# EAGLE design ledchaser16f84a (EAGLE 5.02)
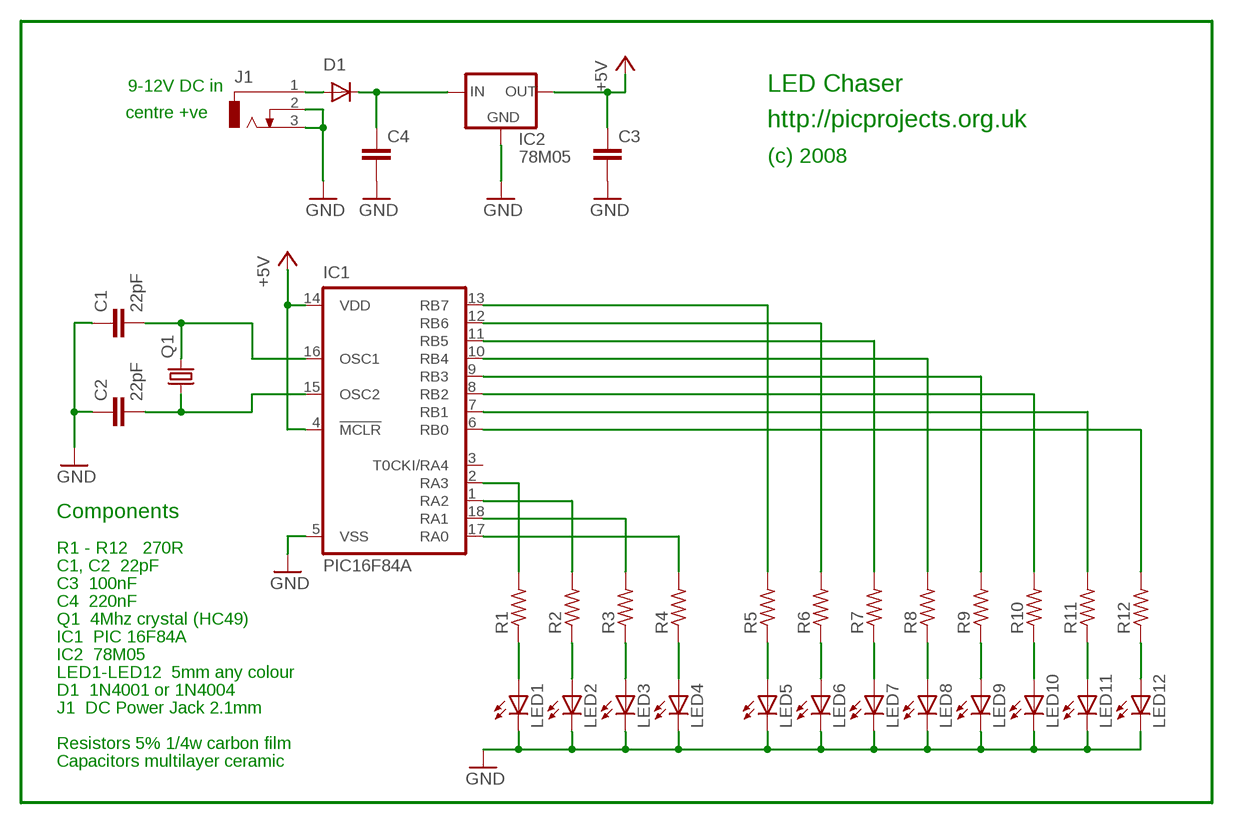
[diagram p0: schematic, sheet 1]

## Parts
C1  22pF  C-EU025-024X044  [C025-024X044]
C2  22pF  C-EU025-024X044  [C025-024X044]
C3  C-EU025-040X050  [C025-040X050]
C4  C-EU025-040X050  [C025-040X050]
D1  1N4004  [DO41-10]
IC1  PIC16F84A  PIC16F83P  [DIL18]
IC2  78M05  78XXL  [78XXL]
J1  DCJ0202  [DCJ0202]
LED1  LED5MM  [LED5MM]
LED2  LED5MM  [LED5MM]
LED3  LED5MM  [LED5MM]
LED4  LED5MM  [LED5MM]
LED5  LED5MM  [LED5MM]
LED6  LED5MM  [LED5MM]
LED7  LED5MM  [LED5MM]
LED8  LED5MM  [LED5MM]
LED9  LED5MM  [LED5MM]
LED10  LED5MM  [LED5MM]
LED11  LED5MM  [LED5MM]
LED12  LED5MM  [LED5MM]
Q1  CRYSTALHC49S  [HC49/S]
R1  R-US_0207/12  [0207/12]
R2  R-US_0207/12  [0207/12]
R3  R-US_0207/12  [0207/12]
R4  R-US_0207/12  [0207/12]
R5  R-US_0207/12  [0207/12]
R6  R-US_0207/12  [0207/12]
R7  R-US_0207/12  [0207/12]
R8  R-US_0207/12  [0207/12]
R9  R-US_0207/12  [0207/12]
R10  R-US_0207/12  [0207/12]
R11  R-US_0207/12  [0207/12]
R12  R-US_0207/12  [0207/12]

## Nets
+5V: C3.1 IC1.4(!MCLR) IC1.14(VDD) IC2.OUT
GND: C1.1 C2.1 C3.2 C4.2 IC1.5(VSS) IC2.GND J1.2 J1.3 LED1.K(C) LED2.K(C) LED3.K(C) LED4.K(C) LED5.K(C) LED6.K(C) LED7.K(C) LED8.K(C) LED9.K(C) LED10.K(C) LED11.K(C) LED12.K(C)
N$1: LED1.A R1.1
N$2: C2.2 IC1.15(OSC2) Q1.1
N$3: C1.2 IC1.16(OSC1) Q1.2
N$4: LED2.A R2.1
N$5: LED3.A R3.1
N$6: LED4.A R4.1
N$7: LED5.A R5.1
N$8: LED6.A R6.1
N$9: LED7.A R7.1
N$10: LED8.A R8.1
N$11: LED9.A R9.1
N$12: LED10.A R10.1
N$13: LED11.A R11.1
N$14: LED12.A R12.1
N$15: IC1.17(RA0) R4.2
N$16: IC1.18(RA1) R3.2
N$17: IC1.1(RA2) R2.2
N$18: IC1.2(RA3) R1.2
N$19: IC1.6(RB0) R12.2
N$20: IC1.7(RB1) R11.2
N$21: IC1.8(RB2) R10.2
N$22: IC1.9(RB3) R9.2
N$23: IC1.10(RB4) R8.2
N$24: IC1.11(RB5) R7.2
N$25: IC1.12(RB6) R6.2
N$26: IC1.13(RB7) R5.2
N$27 [power]: D1.A J1.1
N$28 [power]: C4.1 D1.C IC2.IN
Unconnected: IC1.3(T0CKI/RA4)

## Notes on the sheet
- 9-12V DC in | LED Chaser
- centre +ve
- http://picprojects.org.uk
- (c) 2008
- Components
- R1 - R12   270R
- C1, C2  22pF
- C3  100nF
- C4  220nF
- Q1  4Mhz crystal (HC49)
- IC1  PIC 16F84A
- IC2  78M05
- LED1-LED12  5mm any colour
- D1  1N4001 or 1N4004
- J1  DC Power Jack 2.1mm
- Resistors 5% 1/4w carbon film
- Capacitors multilayer ceramic

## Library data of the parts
C1-C4 = rcl:C-EU: CAPACITOR, European symbol
D1 = diode:1N4004: DIODE
IC1 = microchip:PIC16F8*: MICROCONTROLLER 8-Bit PIC16F8X Family - CMOS Flash/EEPROM Pin Compatible : PIC16F83, PIC16CR83, PIC16F84A, PIC16CR84 see also PIC16C*
IC2 = v-reg:78XXL: VOLTAGE REGULATOR
J1 = con-jack:DCJ0202: DC POWER JACK Source: DCJ0202.pdf
LED1-LED12 = led:LED: LED
Q1 = crystal:CRYSTAL: CRYSTAL
R1-R12 = rcl:R-US_: RESISTOR, American symbol

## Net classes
0 default: width 0.61 mm
1 power: width 0.914 mm

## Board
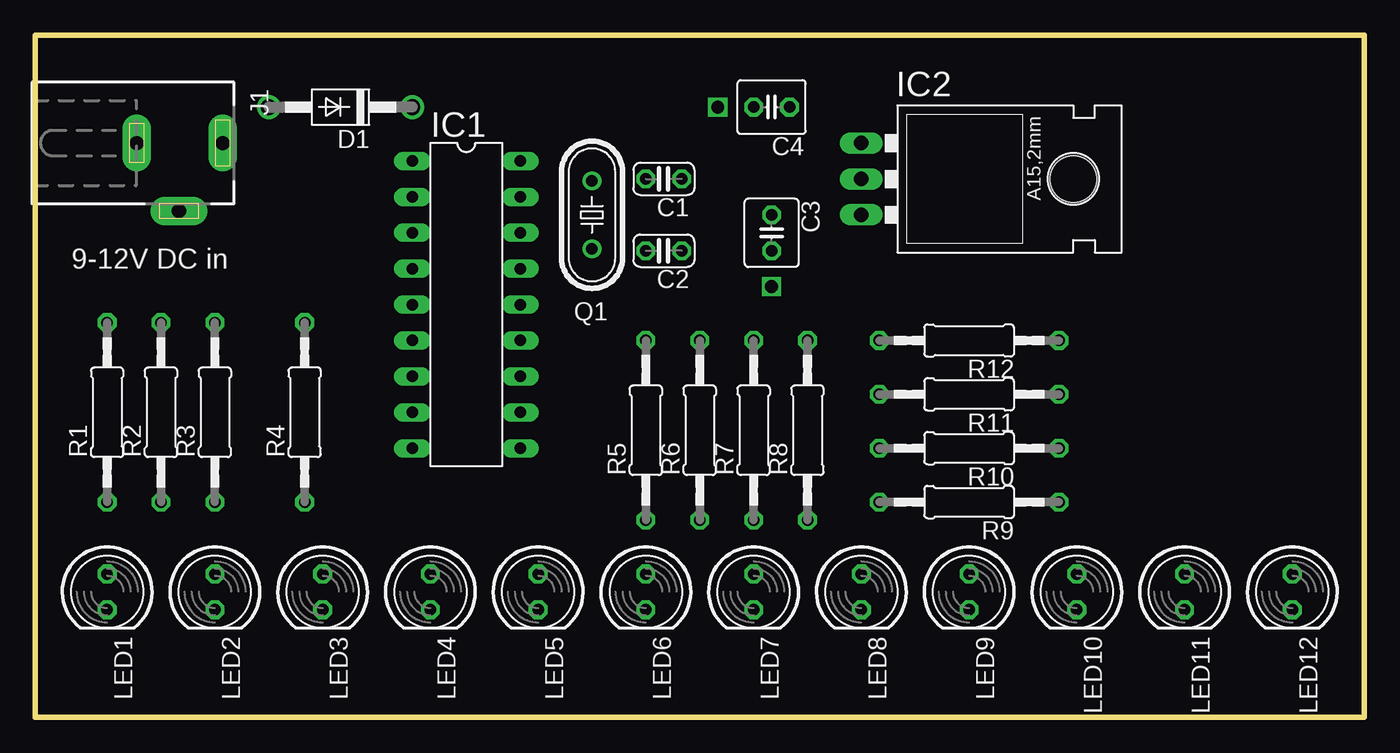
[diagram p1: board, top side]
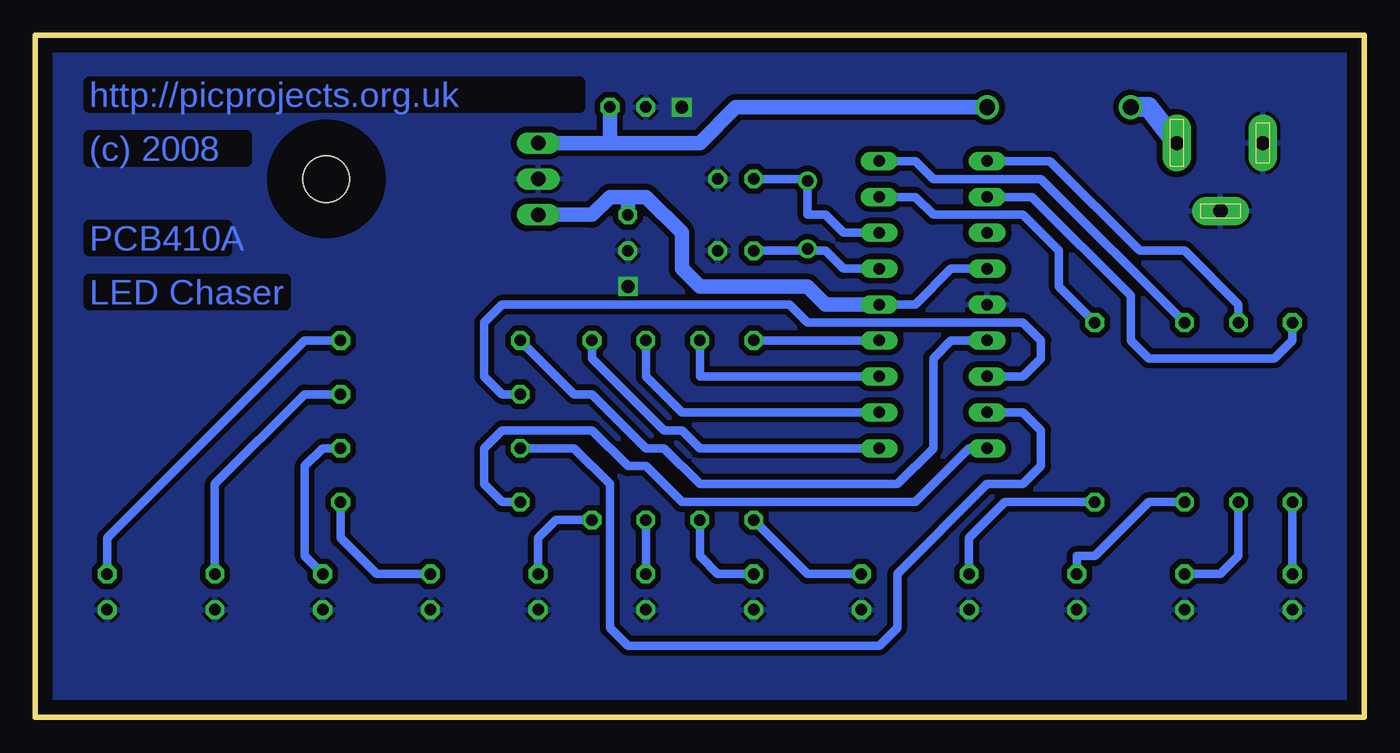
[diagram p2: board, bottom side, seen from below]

Size 93.98 x 48.26 mm. Coordinates in mm from the lower left corner, seen from the top.
Outline: 0,48.26 93.98,48.26 93.98,0 0,0 0,48.26
Copper layers (1*16): Top 0.035mm / dielectric 1.5mm / Bottom 0.035mm
Design rules "default *": minimum track width 10mil, minimum drill 24mil, track to track 16mil, track to pad 16mil, pad to pad 8mil, via to via 8mil, smd to smd 8mil, copper to edge 40mil, drill to drill 8mil, minimum pad ring 10mil, minimum via ring 8mil, stop-mask expansion 4mil, vias tented up to drill 0mil, thermal gap 10mil

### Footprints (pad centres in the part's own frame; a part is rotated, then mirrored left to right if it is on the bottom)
C025-024X044 = drill 0.813 octagon: 1 -1.27,0; 2 1.27,0
C025-040X050 = drill 0.813 octagon: 1 -1.27,0; 2 1.27,0
DO41-10 = drill 1.118 round: A 5.08,0; C -5.08,0
DIL18 = drill 0.813 long: 1 -10.16,-3.81; 2 -7.62,-3.81; 3 -5.08,-3.81; 4 -2.54,-3.81; 5 0,-3.81; 6 2.54,-3.81; 7 5.08,-3.81; 8 7.62,-3.81; 9 10.16,-3.81; 10 10.16,3.81; 11 7.62,3.81; 12 5.08,3.81; 13 2.54,3.81; 14 0,3.81; 15 -2.54,3.81; 16 -5.08,3.81; 17 -7.62,3.81; 18 -10.16,3.81
78XXL = drill 1.016 long: GND 0,-3.81; IN -2.54,-3.81; OUT 2.54,-3.81 | hole 3.302: 0,11.176
DCJ0202 = drill 1 pad 2 long: 1 0,3.1; 2 4.8,0; 3 0,-3
LED5MM = drill 0.813 octagon: A -1.27,0; K 1.27,0
HC49/S = drill 0.813 round: 1 -2.413,0; 2 2.413,0
0207/12 = drill 0.813 octagon: 1 -6.35,0; 2 6.35,0

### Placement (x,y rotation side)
C1  44.45,38.1 180 top
C2  44.45,33.02 180 top
C3  52.07,34.29 270 top
C4  52.07,43.18 180 top
D1  21.59,43.18 180 top
IC1  30.48,29.21 270 top
IC2  62.23,38.1 270 top
J1  10.16,40.64 270 top
LED1  5.08,8.89 270 top
LED2  12.7,8.89 270 top
LED3  20.32,8.89 270 top
LED4  27.94,8.89 270 top
LED5  35.56,8.89 270 top
LED6  43.18,8.89 270 top
LED7  50.8,8.89 270 top
LED8  58.42,8.89 270 top
LED9  66.04,8.89 270 top
LED10  73.66,8.89 270 top
LED11  81.28,8.89 270 top
LED12  88.9,8.89 270 top
Q1  39.37,35.56 90 top
R1  5.08,21.59 90 top
R2  8.89,21.59 90 top
R3  12.7,21.59 90 top
R4  19.05,21.59 90 top
R5  43.18,20.32 90 top
R6  46.99,20.32 90 top
R7  50.8,20.32 90 top
R8  54.61,20.32 90 top
R9  66.04,15.24 180 top
R10  66.04,19.05 180 top
R11  66.04,22.86 180 top
R12  66.04,26.67 180 top

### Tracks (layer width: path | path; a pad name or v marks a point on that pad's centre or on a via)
+5V
  Bottom 0.61: IC1.4 29.21,31.75 31.75,29.21 IC1.14
  Bottom 1.016: IC2.OUT 54.61,35.56 53.34,36.83 52.07,36.83 | IC1.14 38.1,29.21 39.37,30.48 46.99,30.48 48.26,31.75 48.26,34.29 50.8,36.83 52.07,36.83 | 52.07,36.83 C3.1
GND  (via drill 0.9)
  other vias: 48.26,43.18 52.07,30.48
  pour Bottom: 0,1.27 93.98,1.27 93.98,48.26 0,48.26
N$1
  Bottom 0.61: LED1.A R1.1
N$2
  Bottom 0.61: 39.37,33.02 38.1,33.02 36.83,31.75 IC1.15 | 39.37,33.02 C2.2 | 39.37,33.02 Q1.1
N$3
  Bottom 0.61: IC1.16 36.83,34.29 38.1,35.56 39.37,35.56 Q1.2 39.37,38.1 C1.2
N$4
  Bottom 0.61: LED2.A 10.16,10.16 8.89,11.43 R2.1
N$5
  Bottom 0.61: R3.1 15.24,15.24 19.05,11.43 20.32,11.43 LED3.A
N$6
  Bottom 0.61: R4.1 25.4,15.24 27.94,12.7 LED4.A
N$7
  Bottom 0.61: LED5.A 39.37,10.16 R5.1
N$8
  Bottom 0.61: LED6.A 45.72,10.16 46.99,11.43 R6.1
N$9
  Bottom 0.61: LED7.A R7.1
N$10
  Bottom 0.61: LED8.A 58.42,12.7 57.15,13.97 R8.1
N$11
  Bottom 0.61: LED9.A 69.85,10.16 72.39,12.7 R9.1
N$12
  Bottom 0.61: LED10.A 74.93,11.43 74.93,17.78 73.66,19.05 R10.1
N$13
  Bottom 0.61: LED11.A 81.28,16.51 74.93,22.86 R11.1
N$14
  Bottom 0.61: LED12.A 88.9,12.7 74.93,26.67 R12.1
N$15
  Bottom 0.61: IC1.17 31.75,36.83 30.48,35.56 24.13,35.56 21.59,33.02 21.59,30.48 R4.2
N$16
  Bottom 0.61: IC1.18 31.75,39.37 30.48,38.1 22.86,38.1 R3.2
N$17
  Bottom 0.61: R2.2 8.89,29.21 12.7,33.02 15.88,33.02 22.23,39.37 IC1.1
N$18
  Bottom 0.61: IC1.2 23.5,36.83 16.51,29.84 16.51,26.67 15.24,25.4 6.35,25.4 5.08,26.67 R1.2
N$19
  Bottom 0.61: R12.2 55.88,22.86 54.61,22.86 50.8,19.05 49.53,19.05 46.99,16.51 33.02,16.51 30.48,19.05 30.48,25.4 29.21,26.67 IC1.6
N$20
  Bottom 0.61: R11.2 60.96,22.86 62.23,24.13 62.23,27.94 60.96,29.21 40.64,29.21 39.37,27.94 24.13,27.94 22.86,26.67 22.86,25.4 24.13,24.13 IC1.7
N$21
  Bottom 0.61: R10.2 55.88,19.05 53.34,16.51 53.34,6.35 52.07,5.08 34.29,5.08 33.02,6.35 33.02,10.16 26.67,16.51 24.13,16.51 22.86,17.78 22.86,20.32 24.13,21.59 IC1.8
N$22
  Bottom 0.61: R9.2 60.96,15.24 62.23,16.51 62.23,19.05 60.96,20.32 54.61,20.32 52.07,17.78 50.8,17.78 48.26,15.24 31.75,15.24 27.94,19.05 IC1.9
N$23
  Bottom 0.61: R8.2 54.61,25.4 49.53,20.32 48.26,20.32 46.99,19.05 IC1.10
N$24
  Bottom 0.61: R7.2 50.8,24.13 48.26,21.59 IC1.11
N$25
  Bottom 0.61: R6.2 46.99,24.13 IC1.12
N$26
  Bottom 0.61: IC1.13 R5.2
N$27
  Bottom 1.422: D1.A 15.24,43.18 J1.1
N$28
  Bottom 1.016: 53.34,40.64 C4.1 | D1.C 44.45,43.18 46.99,40.64 53.34,40.64 | 53.34,40.64 IC2.IN
N$29
  pour Bottom: 0,1.27 0,48.26

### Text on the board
Bottom: http://picprojects.org.uk | (c) 2008 | PCB410A | LED Chaser
tNames: 9-12V DC in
